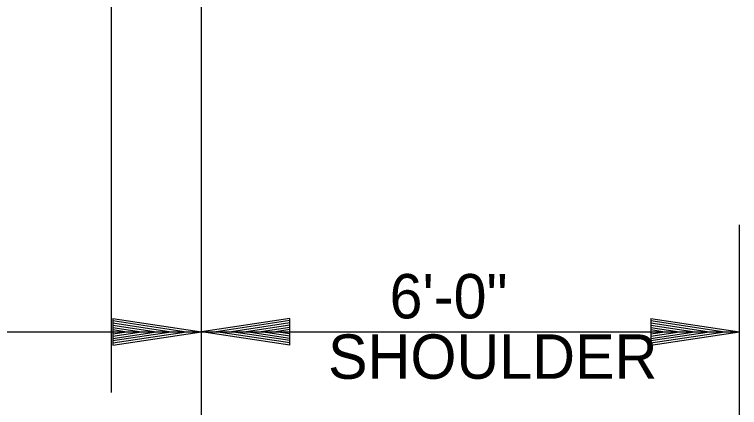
# Model space of a CAD drawing. Extents: x 6125 to 14104, y 8730 to 11067.
# Drawn here: x 9177 to 9340.6, y 10657.5 to 10746 of the extents above; entities that cross this region are included whole.
import ezdxf

# ---------------------------------------------------------------- set-up
doc = ezdxf.new("R2010")
doc.units = 0
doc.layers.add('Stage 1 Construction', color=7, linetype='Continuous')

msp = doc.modelspace()

# ---------------------------------------------------------------- linework, layer by layer
at = {"layer": 'Stage 1 Construction'}
for p, q in [((9219.18, 10637.08), (9219.18, 10928.28)), ((9198.91, 10660.86), (9198.91, 10790.71)), ((9219.18, 10637.08), (9219.18, 10698.6)), ((9340.59, 10543.29), (9340.59, 10698.6)), ((9199.18, 10677.54), (9219.18, 10674.54)), ((9199.18, 10677.54), (9199.18, 10671.54)), ((9199.18, 10677.54), (9219.18, 10674.54)), ((9199.18, 10677.54), (9199.18, 10671.54)), ((9199.18, 10677.04), (9215.84, 10674.54)), ((9199.18, 10677.04), (9215.84, 10674.54)), ((9199.18, 10676.53), (9212.4, 10674.54)), ((9199.18, 10676.53), (9212.4, 10674.54)), ((9199.18, 10676.03), (9209.07, 10674.54)), ((9199.18, 10676.03), (9209.07, 10674.54)), ((9239.18, 10677.54), (9219.18, 10674.54)), ((9239.18, 10677.54), (9219.18, 10674.54)), ((9239.18, 10677.04), (9222.52, 10674.54)), ((9239.18, 10677.04), (9222.52, 10674.54)), ((9239.18, 10676.53), (9225.96, 10674.54)), ((9239.18, 10676.53), (9225.96, 10674.54)), ((9239.18, 10676.03), (9229.29, 10674.54)), ((9239.18, 10676.03), (9229.29, 10674.54)), ((9239.18, 10671.54), (9239.18, 10677.54)), ((9239.18, 10671.54), (9239.18, 10677.54)), ((9320.59, 10677.54), (9340.59, 10674.54)), ((9320.59, 10677.54), (9320.59, 10671.54)), ((9320.59, 10677.04), (9337.25, 10674.54)), ((9320.59, 10676.53), (9333.81, 10674.54)), ((9320.59, 10676.03), (9330.48, 10674.54)), ((9005.34, 10674.54), (9219.18, 10674.54)), ((9199.18, 10675.51), (9205.68, 10674.54)), ((9199.18, 10675.51), (9205.68, 10674.54)), ((9199.18, 10675.01), (9202.34, 10674.54)), ((9199.18, 10675.01), (9202.34, 10674.54)), ((9199.18, 10671.54), (9219.18, 10674.54)), ((9199.18, 10673.56), (9205.68, 10674.54)), ((9199.18, 10672.55), (9212.4, 10674.54)), ((9199.18, 10672.04), (9215.84, 10674.54)), ((9199.18, 10673.05), (9209.07, 10674.54)), ((9199.18, 10674.07), (9202.34, 10674.54)), ((9199.18, 10671.54), (9219.18, 10674.54)), ((9199.18, 10673.56), (9205.68, 10674.54)), ((9199.18, 10672.55), (9212.4, 10674.54)), ((9199.18, 10672.04), (9215.84, 10674.54)), ((9199.18, 10673.05), (9209.07, 10674.54)), ((9199.18, 10674.07), (9202.34, 10674.54)), ((9219.18, 10674.54), (9340.59, 10674.54)), ((9239.18, 10671.54), (9219.18, 10674.54)), ((9239.18, 10671.54), (9219.18, 10674.54)), ((9239.18, 10672.04), (9222.52, 10674.54)), ((9239.18, 10672.04), (9222.52, 10674.54)), ((9239.18, 10672.55), (9225.96, 10674.54)), ((9239.18, 10672.55), (9225.96, 10674.54)), ((9239.18, 10673.05), (9229.29, 10674.54)), ((9239.18, 10673.05), (9229.29, 10674.54)), ((9239.18, 10675.52), (9232.68, 10674.54)), ((9239.18, 10675.52), (9232.68, 10674.54)), ((9239.18, 10673.57), (9232.68, 10674.54)), ((9239.18, 10673.57), (9232.68, 10674.54)), ((9239.18, 10675.01), (9236.02, 10674.54)), ((9239.18, 10675.01), (9236.02, 10674.54)), ((9239.18, 10674.07), (9236.02, 10674.54)), ((9239.18, 10674.07), (9236.02, 10674.54)), ((9320.59, 10675.51), (9327.09, 10674.54)), ((9320.59, 10675.01), (9323.75, 10674.54)), ((9320.59, 10671.54), (9340.59, 10674.54)), ((9320.59, 10673.56), (9327.09, 10674.54)), ((9320.59, 10672.55), (9333.81, 10674.54)), ((9320.59, 10672.04), (9337.25, 10674.54)), ((9320.59, 10673.05), (9330.48, 10674.54)), ((9320.59, 10674.07), (9323.75, 10674.54))]:
    msp.add_line(p, q, dxfattribs=at)

# ---------------------------------------------------------------- texts
for s, p in [('6\'-0"', (9261.64, 10677.54)), ('SHOULDER', (9247.76, 10663.94))]:
    msp.add_text(s, height=10, dxfattribs=at).set_placement(p)

doc.saveas('drawing.dxf')
